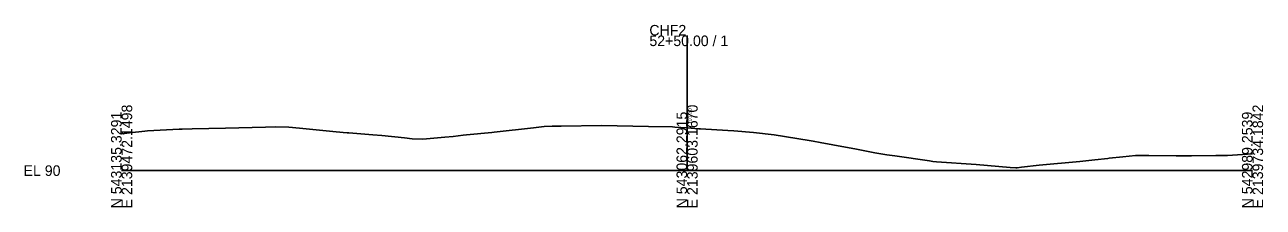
# Model space of a CAD drawing. Extents: x -12831 to 2303, y -10 to 39065.
# Drawn here: x 1974.3 to 2302.8, y 4990.3 to 5038.6 of the extents above; entities that cross this region are included whole.
import ezdxf

# ---------------------------------------------------------------- set-up
doc = ezdxf.new("R2010")
doc.units = 0
for name, color, linetype in [('RD_GPK_XS_Cell', 7, 'Continuous'), ('RD_XS_ExGround', 7, 'Continuous'), ('RD_XS_TX_Elev_EX', 7, 'Continuous')]:
    doc.layers.add(name, color=color, linetype=linetype)

msp = doc.modelspace()

# ---------------------------------------------------------------- linework, layer by layer
at = {"layer": 'RD_GPK_XS_Cell'}
for p, q in [((2150, 5000), (2150, 5035.79)), ((2000, 5000), (2150, 5000)), ((2150, 5000), (2300, 5000))]:
    msp.add_line(p, q, dxfattribs=at)
at = {"layer": 'RD_XS_ExGround'}
for p, q in [((2002.05, 5009.98), (2006.14, 5010.43)), ((2006.14, 5010.43), (2006.84, 5010.52)), ((2006.84, 5010.52), (2015.23, 5010.94)), ((2015.23, 5010.94), (2016.09, 5010.99)), ((2016.09, 5010.99), (2018.68, 5011.05)), ((2018.68, 5011.05), (2027.6, 5011.28)), ((2027.6, 5011.28), (2038.17, 5011.55)), ((2038.17, 5011.55), (2040.95, 5011.61)), ((2040.95, 5011.61), (2044.39, 5011.49)), ((2044.39, 5011.49), (2047.19, 5011.24)), ((2047.19, 5011.24), (2056.05, 5010.35)), ((2056.05, 5010.35), (2058.74, 5010.14)), ((2058.74, 5010.14), (2059.83, 5010.03)), ((2091.51, 5009.44), (2098.23, 5010.13)), ((2098.23, 5010.13), (2098.86, 5010.15)), ((2098.86, 5010.15), (2109.24, 5011.29)), ((2109.24, 5011.29), (2112.06, 5011.72)), ((2112.06, 5011.72), (2114.19, 5011.78)), ((2114.19, 5011.78), (2114.75, 5011.79)), ((2114.75, 5011.79), (2116.61, 5011.81)), ((2116.61, 5011.81), (2127.31, 5011.93)), ((2127.31, 5011.93), (2139.81, 5011.68)), ((2139.81, 5011.68), (2146.17, 5011.56)), ((2146.17, 5011.56), (2146.71, 5011.52)), ((2146.71, 5011.52), (2150, 5011.3)), ((2150, 5011.3), (2153.12, 5011.09)), ((2153.12, 5011.09), (2153.59, 5011.07)), ((2153.59, 5011.07), (2160.81, 5010.62)), ((2160.81, 5010.62), (2162.44, 5010.5)), ((2162.44, 5010.5), (2167.66, 5010.07)), ((2000, 5009.75), (2002.05, 5009.98)), ((2059.83, 5010.03), (2060.27, 5009.99)), ((2060.27, 5009.99), (2066.67, 5009.52)), ((2066.67, 5009.52), (2069.05, 5009.27)), ((2069.05, 5009.27), (2075.02, 5008.65)), ((2075.02, 5008.65), (2077.05, 5008.43)), ((2077.05, 5008.43), (2079.89, 5008.29)), ((2079.89, 5008.29), (2085.73, 5008.88)), ((2085.73, 5008.88), (2087.96, 5009.08)), ((2087.96, 5009.08), (2090.64, 5009.35)), ((2090.64, 5009.35), (2091.51, 5009.44)), ((2167.66, 5010.07), (2173.13, 5009.51)), ((2173.13, 5009.51), (2182.41, 5007.97)), ((2182.41, 5007.97), (2183.46, 5007.82)), ((2183.46, 5007.82), (2185.29, 5007.47)), ((2185.29, 5007.47), (2191.99, 5006.17)), ((2191.99, 5006.17), (2194.46, 5005.74)), ((2194.46, 5005.74), (2199.83, 5004.75)), ((2199.83, 5004.75), (2203.03, 5004.16)), ((2203.03, 5004.16), (2205.11, 5003.92)), ((2205.11, 5003.92), (2214.35, 5002.57)), ((2261.93, 5003.31), (2265.57, 5003.66)), ((2265.57, 5003.66), (2268.97, 5004.03)), ((2268.97, 5004.03), (2272.47, 5003.99)), ((2272.47, 5003.99), (2279.73, 5003.88)), ((2279.73, 5003.88), (2283.83, 5003.88)), ((2283.83, 5003.88), (2290.29, 5004.01)), ((2290.29, 5004.01), (2293.36, 5003.98)), ((2293.36, 5003.98), (2300, 5004.46)), ((2214.35, 5002.57), (2215.21, 5002.45)), ((2215.21, 5002.45), (2216.2, 5002.36)), ((2216.2, 5002.36), (2226.69, 5001.64)), ((2226.69, 5001.64), (2235.72, 5000.85)), ((2235.72, 5000.85), (2237.19, 5000.73)), ((2237.19, 5000.73), (2237.56, 5000.74)), ((2237.56, 5000.74), (2238.68, 5000.87)), ((2238.68, 5000.87), (2243.41, 5001.4)), ((2243.41, 5001.4), (2254.17, 5002.43)), ((2254.17, 5002.43), (2258.19, 5002.83)), ((2258.19, 5002.83), (2261.58, 5003.24)), ((2261.58, 5003.24), (2261.93, 5003.31))]:
    msp.add_line(p, q, dxfattribs=at)

# ---------------------------------------------------------------- texts
at = {"layer": 'RD_GPK_XS_Cell'}
for s, p in [('CHF2', (2140, 5035.79)), ('52+50.00 / 1', (2140, 5032.99)), ('EL 90', (1974, 4998.6))]:
    msp.add_text(s, height=2.8, dxfattribs=at).set_placement(p)
for s, p in [('E 2139472.1498', (2002.8, 4990)), ('E 2139603.1670', (2152.8, 4990)), ('E 2139734.1842', (2302.8, 4990)), ('N 543135.3291', (2000, 4990)), ('N 543062.2915', (2150, 4990)), ('N 542989.2539', (2300, 4990))]:
    msp.add_text(s, height=2.8, rotation=90, dxfattribs=at).set_placement(p)
at = {"layer": 'RD_XS_TX_Elev_EX'}
msp.add_text('101.30', height=1, rotation=90, dxfattribs=at).set_placement((2151.25, 5012.3))

doc.saveas('drawing.dxf')
